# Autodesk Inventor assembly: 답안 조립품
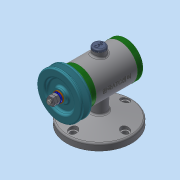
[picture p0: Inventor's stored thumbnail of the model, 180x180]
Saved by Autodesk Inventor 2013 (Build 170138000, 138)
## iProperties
Created: 2018-12
Part Number: 답안 조립품
Document SubType Name: Assembly
Designer: dgall
Author: dgall
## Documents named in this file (15)
- C:\Users\dgall\Desktop\481207V1005\답안 조립품.iam
- C:\Users\dgall\Desktop\481207V1005\본체.ipt
- C:\Users\dgall\Desktop\481207V1005\V벨트풀리.ipt
- C:\Users\dgall\Desktop\481207V1005\고무캡.ipt
- C:\Users\dgall\Desktop\481207V1005\너트 M8.ipt
- 너트 M8.ipt
- C:\Users\dgall\Desktop\481207V1005\뒤커버.ipt
- C:\Users\dgall\Desktop\481207V1005\베어링 15 x 32 x 9.ipt
- C:\Users\dgall\Desktop\481207V1005\볼트 M4 x 12.ipt
- C:\Users\dgall\Desktop\481207V1005\스프링와셔 8.ipt
- C:\Users\dgall\Desktop\481207V1005\앞커버.ipt
- C:\Users\dgall\Desktop\481207V1005\오일 실 15 25 7.ipt
- C:\Users\dgall\Desktop\481207V1005\와셔 8x17.ipt
- C:\Users\dgall\Desktop\481207V1005\축.ipt
- C:\Users\dgall\Desktop\481207V1005\키 3 x 3 x 12.ipt
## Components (2 placed, 2 different names)
1. V벨트풀리:1
2. 고무캡:2
